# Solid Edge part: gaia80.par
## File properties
Title: Gaia 80 87,5x39,5 cm
Author: DESYS
Template: Normal.par
Last saved by: Luca
Revision: 16
Application: Solid Edge
Tipo di contenuto documento: 0
Accuracy: 0,990
Document Number: 8033
Revision: 0
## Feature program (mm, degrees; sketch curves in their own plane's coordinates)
lofted protrusion "unnamed LoftedProtrusion 1"
lofted cutout "unnamed LoftedCutout 1"
sketch for "unnamed Protrusion 1" #1 plane through (0, 0, 0) normal (0, 0, 1) x-axis (1, 0, 0)
  line (-420, -180) -> (420, -180)
  line (420, -180) -> (420, 180)
  line (420, 180) -> (-420, 180)
  line (-420, 180) -> (-420, -180)
sketch for "unnamed Protrusion 1" #2 plane through (0, 0, 0) normal (0, 0, 1) x-axis (1, 0, 0)
  line (-437.5, -197.5) -> (437.5, -197.5)
  line (437.5, -197.5) -> (437.5, 197.5)
  line (437.5, 197.5) -> (-437.5, 197.5)
  line (-437.5, 197.5) -> (-437.5, -197.5)
  dimension (linear) = 437.5
extrude "unnamed Protrusion 1" add finite 15 along -normal
sketch for "unnamed Protrusion 2" plane through (0, -180, -7.5) normal (0, -1, 0) x-axis (1, 0, 0)
  line (-420, -7.5) -> (420, -7.5)
extrude "unnamed Protrusion 2" add through
sketch for "ExtrudedCutout_2" plane through (0, 0, -155) normal (0, 0, -1) x-axis (-1, 0, 0)
  line (-300, -65) -> (300, -65)
  line (300, -65) -> (300, 130)
  line (300, 130) -> (-300, 130)
  line (-300, 130) -> (-300, -65)
  dimension (linear) = 300
  dimension (linear) = 300
extrude "ExtrudedCutout_2" cut finite 29 along -normal  Treatment1_DraftAngle = 30 deg
sketch for "ExtrudedCutout_1" plane through (0, -394, 0) normal (0, -1, 0) x-axis (1, 0, 0)
  line (92.6707, -163.631) -> (50, -15)
  line (50, -15) -> (-50, -15)
  line (-50, -15) -> (-97.4177, -181.7658)
  dimension (linear) = 50
extrude "ExtrudedCutout_1" cut along -normal  Profile_Plane1_Distance = 394 mm
sketch for "ExtrudedCutout_3" plane through (0, -388, 0) normal (0, -1, 0) x-axis (1, 0, 0)
  line (119.568, -126) -> (127.8937, -155)
  line (119.568, -126) -> (-110.432, -126)
  line (-110.432, -126) -> (-118.6777, -155)
  dimension (linear) = 119.568
extrude "ExtrudedCutout_3" cut through along -normal  Profile_Plane1_Distance = 388 mm
sketch for "ExtrudedProtrusion_2" plane through (0, -24.034, -126) normal (0, 0, -1) x-axis (-1, 0, 0)
  circle centre (0, 6.534) radius 35
extrude "ExtrudedProtrusion_2" add finite 30 along +normal
sketch for "ExtrudedProtrusion_5" plane through (0, 0, 0) normal (1, 0, 0) x-axis (0, 1, 0)
  line (0.9326, -126) -> (0.9326, -148)
  line (0.9326, -148) -> (-145.4418, -148)
  arc centre (-145.4418, -126) radius 22 from (-166.6761, -131.7537) to (-145.4418, -148) ccw
  line (-166.6761, -131.7537) -> (-193.2908, -33.5316)
  arc centre (-188.4649, -32.2239) radius 5 from (-193.2908, -33.5316) to (-188.4649, -27.2239) cw
  line (-188.4649, -27.2239) -> (-175.8329, -27.2239)
  line (-175.8329, -27.2239) -> (-149.068, -126)
  line (-149.068, -126) -> (0.9326, -126)
extrude "ExtrudedProtrusion_5" add finite 45 symmetric
sketch for "unnamed Cutout 1" plane through (0, -11.5, -110) normal (0, 0, 1) x-axis (-1, 0, 0)
  circle centre (0, 6) radius 22.5
extrude "unnamed Cutout 1" cut through along -normal
sketch for "Foro_4" plane through (-154.2097, -172.8226, -85) normal (0, -0.995946, -0.089956) x-axis (1, 0, 0)
  hole centre (-197.7097, 20.3461) bore radius 7.5
hole "Foro_4" diameter 15 finite
sketch for "Foro_5" plane through (154.2097, -172.8226, -85) normal (0, -0.995946, -0.089956) x-axis (1, 0, 0)
  hole centre (212.7097, 31.8753) bore radius 7.5
  dimension (linear) = 212.7097
hole "Foro_5" diameter 15 finite
fillet "Rotondo_2" radius 10
fillet "Rotondo_3" radius 25
fillet "Rotondo_4" radius 20
fillet "Rotondo_7" radius 10
fillet "Rotondo_9" radius 5
fillet "Rotondo_10" radius 5
fillet "Rotondo_11" radius 5
fillet "Rotondo_12" radius 5
fillet "Rotondo_13" radius 10
sketch for "ExtrudedCutout_7" plane through (0, -23.3825, -126) normal (0, 0, -1) x-axis (-1, 0, 0)
  line (-42.5, -21.9887) -> (-42.5, -133.4514)
  line (-50.5, -133.4514) -> (-42.5, -133.4514)
  line (-50.5, -133.4514) -> (-50.5, -26.605)
  arc centre (-93.7, -26.605) radius 43.2 from (-55.5847, -6.2711) to (-50.5, -26.605) cw
  arc centre (0, 23.3825) radius 63 from (-55.5847, -6.2711) to (55.5847, -6.2711) cw
  arc centre (93.7, -26.605) radius 43.2 from (55.5847, -6.2711) to (50.5, -26.605) ccw
  line (50.5, -133.4514) -> (50.5, -26.605)
  line (42.5, -133.4514) -> (50.5, -133.4514)
  line (42.5, -21.9887) -> (42.5, -133.4514)
  arc centre (76.092, -21.9887) radius 33.592 from (47.2397, -4.785) to (42.5, -21.9887) ccw
  arc centre (0, 23.3825) radius 55 from (-47.2397, -4.785) to (47.2397, -4.785) cw
  arc centre (-76.092, -21.9887) radius 33.592 from (-47.2397, -4.785) to (-42.5, -21.9887) cw
extrude "ExtrudedCutout_7" cut finite 4 along -normal
fillet "Rotondo_14" radius 2
fillet "Rotondo_16" radius 10
fillet "Rotondo_17" radius 5
fillet "Rotondo_18" radius 5
sketch for "Foro_6" plane through (0, 0, -155) normal (0, 0, -1) x-axis (-1, 0, 0)
  hole centre (355.3328, 132.322) bore radius 10
hole "Foro_6" finite
sketch for "unnamed Hole 1" plane through (0, 0, -155) normal (0, 0, -1) x-axis (-1, 0, 0)
hole "unnamed Hole 1" finite
pattern "unnamed Pattern 1" of "Foro_6", "unnamed Hole 1"
sketch for "Foro_9" plane through (0, 0, 0) normal (0, -1, 0) x-axis (1, 0, 0)
hole "Foro_9" finite
fillet "Rotondo_22" radius 5
Other named dimensions: "ExtrudedSurface_1": Profile_Plane1_Distance = 375 mm; FiniteDepth = 750 mm
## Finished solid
Body 1: sheet body, 1 face, 4 edges, 4 vertices.
  Faces by surface: plane 1
  Edges by curve: line 4
Body 2: solid body, 234 faces, 501 edges, 270 vertices.
  Faces by surface: cylinder 99, blend 50, plane 37, sphere 25, torus 23
  Edges by curve: circle 214, line 182, ellipse 79, intersection 26
Bounding box of the edges (mm; curved faces can reach further): 875.000 x 397.984 x 270.931, from (-437.5, -200.484, -207.1797) to (437.5, 197.5, 63.7514).
Cylindrical faces by radius (mm): R2 x8, R5 x39, R7.5 x2, R9.5 x1, R10 x38, R22 x1, R22.5 x1, R25 x8, R35 x1
Toroidal faces (ring radius, tube radius in mm): R5 r5 x4, R10 r5 x1, R17 r5 x2, R30 r5 x1, R31.592 r2 x2, R35.592 r2 x2, R39.798 r5 x1, R40 r5 x1, R41.2 r2 x2, R42.5 r20 x1, R45.2 r2 x2, R53 r2 x1, R57 r2 x1, R61 r2 x1, R65 r2 x1
Spherical faces by radius (mm): R5 x8, R10 x13, R25 x4
Planar faces by outward normal: +x 1, +y 1, +z 3, -x 1, -z 9, oblique 22
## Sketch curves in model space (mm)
line (340, -141.5, -110) -> (340, 118.5, -110)
line (340, 118.5, -110) -> (-340, 118.5, -110)
line (-340, 118.5, -110) -> (-340, -141.5, -110)
line (-340, -141.5, -110) -> (340, -141.5, -110)
line (420, -180, 0) -> (420, 180, 0)
line (420, 180, 0) -> (-420, 180, 0)
line (-420, 180, 0) -> (-420, -180, 0)
line (-420, -180, 0) -> (420, -180, 0)
line (383.5, -166.5, -155) -> (383.5, 166.5, -155)
line (383.5, 166.5, -155) -> (-383.5, 166.5, -155)
line (-383.5, 166.5, -155) -> (-383.5, -166.5, -155)
line (-383.5, -166.5, -155) -> (383.5, -166.5, -155)
line (420.5, -180.5, 0) -> (420.5, 180.5, 0)
line (420.5, 180.5, 0) -> (-420.5, 180.5, 0)
line (-420.5, 180.5, 0) -> (-420.5, -180.5, 0)
line (-420.5, -180.5, 0) -> (420.5, -180.5, 0)
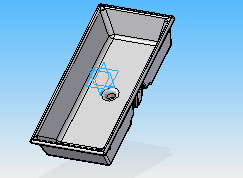
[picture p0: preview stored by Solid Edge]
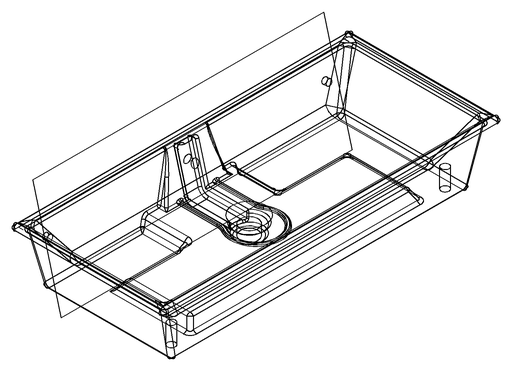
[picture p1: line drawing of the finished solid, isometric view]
